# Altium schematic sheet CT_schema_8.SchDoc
size 254 x 194 mm
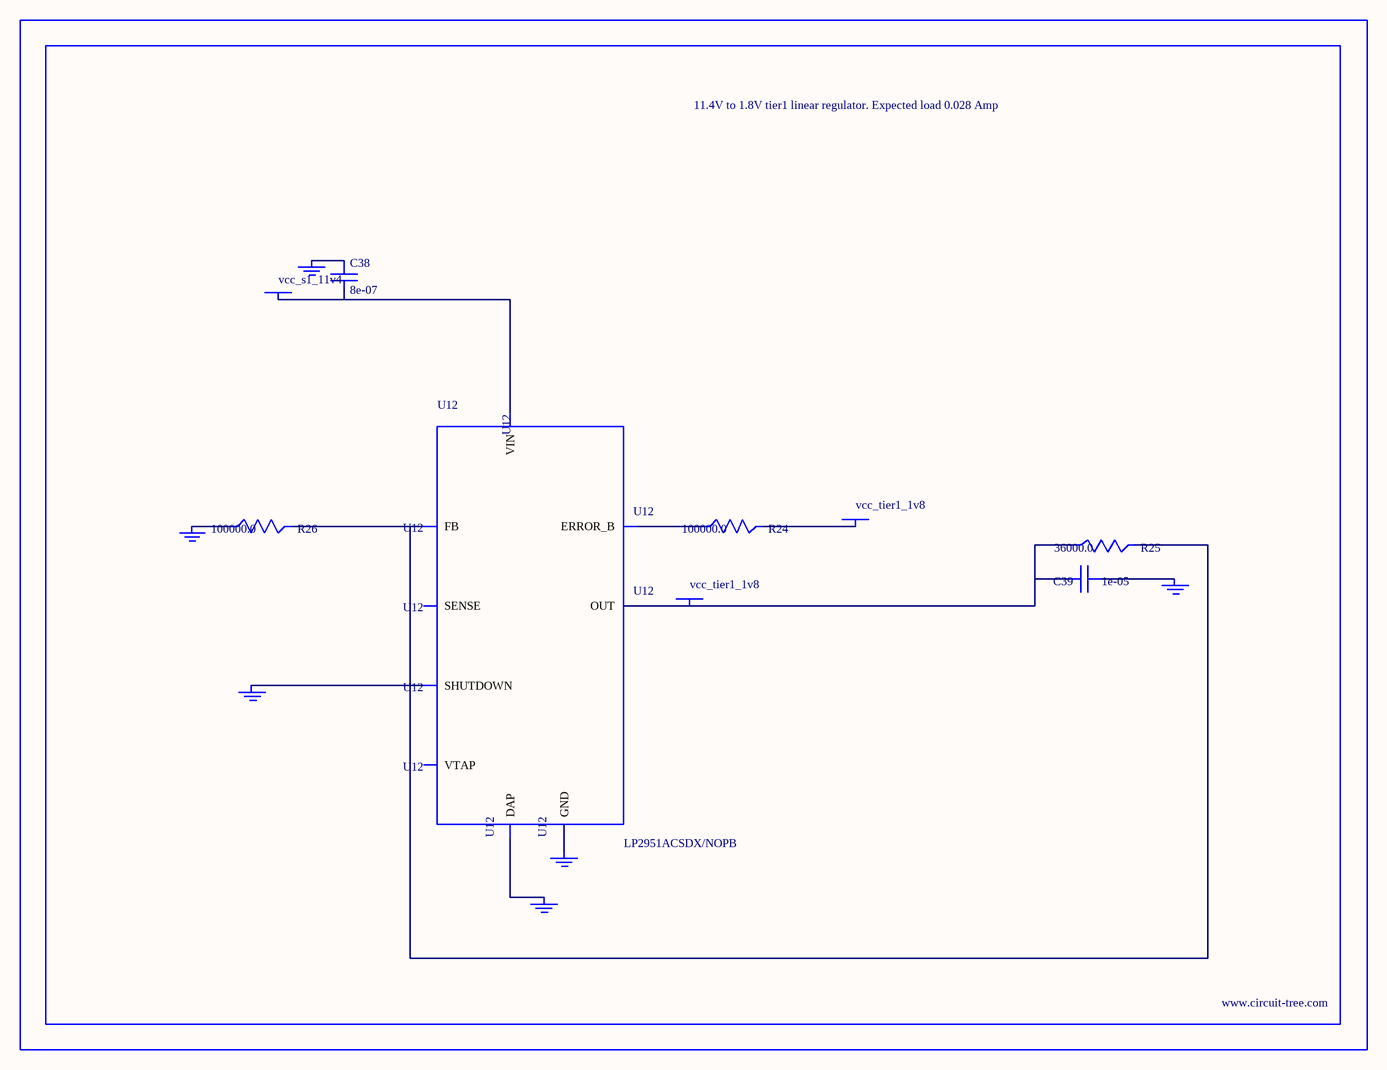
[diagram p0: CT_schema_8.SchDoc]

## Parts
BORDER7  (no value)
C38  8e-07  [R0603]
C39  1e-05  [C0805]
GND_INSTANCE_7_0  (no value)
GND_INSTANCE_7_1  (no value)
GND_INSTANCE_7_2  (no value)
GND_INSTANCE_7_3  (no value)
GND_INSTANCE_7_4  (no value)
GND_INSTANCE_7_5  (no value)
POWER_INSTANCE_7_0  vcc_tier1_1v8
POWER_INSTANCE_7_1  vcc_s1_11v4
POWER_INSTANCE_7_2  vcc_tier1_1v8
R24  100000.0  [R0603]
R25  36000.0  [R0603]
R26  100000.0  [R0603]
U12  LP2951ACSDX/NOPB  [WSON-8]

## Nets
NetC38_1: C38.1 GND_INSTANCE_7_3.0(GND)
NetC38_2: C38.2 POWER_INSTANCE_7_1.0(PWR) U12.8(VIN)
NetC39_1: C39.1 GND_INSTANCE_7_0.0(GND)
NetC39_2: C39.2 POWER_INSTANCE_7_2.0(PWR) R25.1 U12.1(OUT)
NetGND_INSTANCE_7_1_0: GND_INSTANCE_7_1.0(GND) U12.3(SHUTDOWN)
NetGND_INSTANCE_7_2_0: GND_INSTANCE_7_2.0(GND) R26.1
NetGND_INSTANCE_7_4_0: GND_INSTANCE_7_4.0(GND) U12.PAD(DAP)
NetGND_INSTANCE_7_5_0: GND_INSTANCE_7_5.0(GND) U12.4(GND)
NetPOWER_INSTANCE_7_0_0: POWER_INSTANCE_7_0.0(PWR) R24.2
NetR24_1: R24.1 U12.5(ERROR_B)
NetR25_2: R25.2 R26.2 U12.7(FB)

Not connected (* = marked no-connect by the designer): U12 2(SENSE) 6(VTAP)

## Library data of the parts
BORDER7 = BORDER_PAGE7
C38 = C38
C39 = GRM219R60J106ME19D
GND_INSTANCE_7_0-GND_INSTANCE_7_5 = GND
POWER_INSTANCE_7_0-POWER_INSTANCE_7_2 = PWR
R24 R26 = RC0603JR-07100KL
R25 = RC0603JR-0736KL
